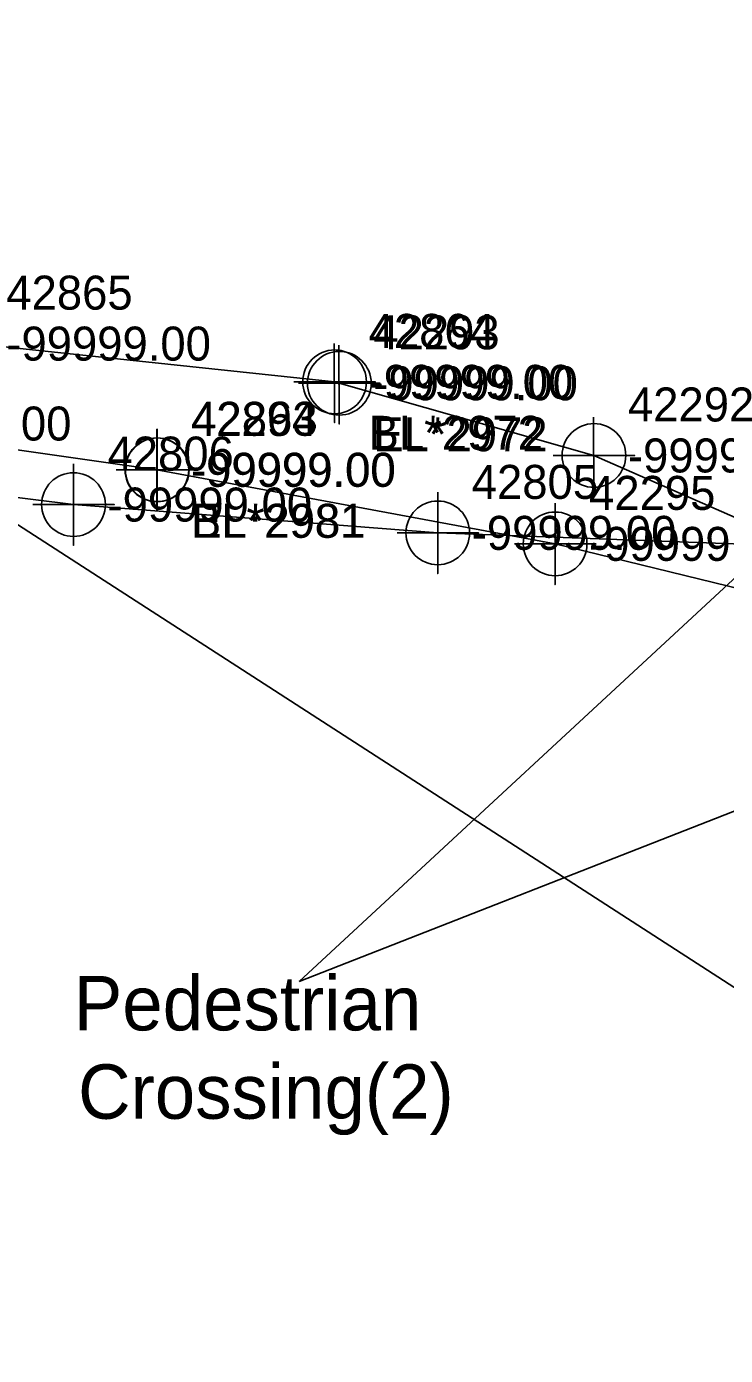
# Model space of a CAD drawing. Extents: x 2083698 to 2094313, y 743246 to 752873.
# Drawn here: x 2093623.5 to 2093674.9, y 746528.4 to 746626.1 of the extents above; entities that cross this region are included whole.
import ezdxf

# ---------------------------------------------------------------- set-up
doc = ezdxf.new("R2010")
doc.units = 0
for name, color, linetype in [('Default Symbol CELL', 7, 'Continuous'), ('Default Symbol Cogo Number', 7, 'Continuous'), ('Exist Property Corner CELL', 7, 'Continuous'), ('Exist Property Iron Pin Leader', 7, 'Continuous'), ('Exist Property Iron Pin Text', 7, 'Continuous'), ('Exist Property Line Leader', 7, 'Continuous'), ('Exist Property Monument Text', 7, 'Continuous'), ('Exist Right of Way Line Leader', 7, 'Continuous'), ('Exist Right of Way Line Text', 7, 'Continuous'), ('Exist Utilities Other Located Object Leader', 7, 'Continuous'), ('Exist Utilities Other Located Object Text', 7, 'Continuous'), ('Exist Utilities Power UG Cable SUE LOS B', 7, 'Continuous'), ('Exist Utilities Power UG Cable SUE LOS C', 7, 'Continuous'), ('Exist Utilities Telephone UG Conduit SUE LOS B', 7, 'Continuous'), ('Exist Utilities TV UG Cable SUE LOS B', 7, 'Continuous'), ('Scratch_Level_2', 7, 'Continuous'), ('Scratch_Level_3', 7, 'Continuous')]:
    doc.layers.add(name, color=color, linetype=linetype)

msp = doc.modelspace()

# ---------------------------------------------------------------- linework, layer by layer
at = {"layer": 'Exist Property Iron Pin Text'}
for points in [[(2093626.933, 746593.955), (2093626.933, 746587.955), (2093626.933, 746590.955), (2093629.933, 746590.955), (2093623.933, 746590.955)], [(2093653.741, 746591.874), (2093653.741, 746585.874), (2093653.741, 746588.874), (2093656.741, 746588.874), (2093650.741, 746588.874)]]:
    msp.add_lwpolyline(points, dxfattribs=at)
for centre in [(2093626.933, 746590.955), (2093653.741, 746588.874)]:
    msp.add_circle(centre, 2.344, dxfattribs=at)
at = {"layer": 'Exist Property Line Leader'}
for points in [[(2093633.071, 746596.51), (2093633.071, 746590.51), (2093633.071, 746593.51), (2093636.071, 746593.51), (2093630.071, 746593.51)], [(2093633.099, 746596.517), (2093633.099, 746590.517), (2093633.099, 746593.517), (2093636.099, 746593.517), (2093630.099, 746593.517)], [(2093662.377, 746591.065), (2093662.377, 746585.065), (2093662.377, 746588.065), (2093665.377, 746588.065), (2093659.377, 746588.065)]]:
    msp.add_lwpolyline(points, dxfattribs=at)
for centre in [(2093633.071, 746593.51), (2093633.099, 746593.517), (2093662.377, 746588.065)]:
    msp.add_circle(centre, 2.344, dxfattribs=at)
at = {"layer": 'Exist Right of Way Line Text'}
for points in [[(2093646.117, 746602.799), (2093646.15, 746596.984), (2093646.133, 746599.984), (2093649.15, 746599.984), (2093643.15, 746599.984)], [(2093646.462, 746602.693), (2093646.495, 746596.878), (2093646.478, 746599.878), (2093649.495, 746599.878), (2093643.495, 746599.878)], [(2093665.202, 746597.384), (2093665.235, 746591.569), (2093665.218, 746594.569), (2093668.235, 746594.569), (2093662.235, 746594.569)]]:
    msp.add_lwpolyline(points, dxfattribs=at)
for centre in [(2093646.15, 746599.984), (2093646.495, 746599.878), (2093665.235, 746594.569)]:
    msp.add_circle(centre, 2.344, dxfattribs=at)
at = {"layer": 'Exist Utilities Other Located Object Leader'}
for p in [(2093687.397, 746596.489), (2093711.996, 746582.69)]:
    msp.add_line(p, (2093643.537, 746555.868), dxfattribs=at)
at = {"layer": 'Exist Utilities Power UG Cable SUE LOS B'}
msp.add_lwpolyline([(2093491.022, 746618.597), (2093492.251, 746617.801), (2093497.044, 746616.267), (2093502.742, 746615.574), (2093516.883, 746611.38), (2093531.704, 746607.278), (2093561.622, 746601.491), (2093580.73, 746597.942), (2093602.772, 746593.943), (2093626.933, 746590.955), (2093653.741, 746588.874), (2093678.786, 746587.934), (2093688.107, 746586.976), (2093698.06, 746587.607), (2093702.807, 746588.319)], dxfattribs=at)
at = {"layer": 'Exist Utilities Power UG Cable SUE LOS C'}
msp.add_lwpolyline([(2091387.723, 747754.046), (2091459.294, 747488.138), (2091734.159, 747369.443), (2092190.287, 747172.263), (2092598.525, 747024.897), (2092972.515, 746889.782), (2093316.778, 746787.162), (2093711.239, 746532.367)], dxfattribs=at)
at = {"layer": 'Exist Utilities Telephone UG Conduit SUE LOS B'}
for points in [[(2093175.22, 746700.688), (2093176.758, 746700.983), (2093181.66, 746699.484), (2093206.905, 746693.771), (2093231.15, 746688.155), (2093256.623, 746681.959), (2093284.725, 746676.591), (2093309.603, 746671.144), (2093335.197, 746665.771), (2093361.049, 746660.734), (2093389.022, 746654.526), (2093416.973, 746647.675), (2093445.691, 746640.123), (2093473.914, 746633.194), (2093499.75, 746627.22), (2093526.174, 746622.184), (2093552.042, 746616.673), (2093579.015, 746608.454), (2093593.796, 746604.937), (2093619.488, 746602.797), (2093646.15, 746599.984)], [(2093722.343, 746560.864), (2093719.996, 746560.006), (2093715.04, 746562.375), (2093709.329, 746567.03), (2093698.957, 746576.197), (2093682.231, 746587.109), (2093665.235, 746594.569), (2093646.495, 746599.878)]]:
    msp.add_lwpolyline(points, dxfattribs=at)
at = {"layer": 'Exist Utilities TV UG Cable SUE LOS B'}
for points in [[(2093211.804, 746678.393), (2093222.599, 746675.974), (2093242.135, 746671.467), (2093264.356, 746666.243), (2093290.813, 746660.779), (2093317.395, 746655.958), (2093343.57, 746650.125), (2093367.056, 746645.407), (2093389.808, 746641.254), (2093404.728, 746638.165), (2093411.824, 746636.762), (2093419.659, 746636.764), (2093441.031, 746633.593), (2093465.697, 746628.877), (2093491.056, 746625.59), (2093517.906, 746620.208), (2093544.749, 746615.204), (2093562.294, 746605.166), (2093582.875, 746601.488), (2093609.224, 746596.916), (2093633.099, 746593.517)], [(2093633.071, 746593.51), (2093662.377, 746588.065), (2093680.365, 746583.676), (2093688.75, 746580.804), (2093702.361, 746567.68), (2093717.615, 746549.774), (2093724.021, 746533.323), (2093724.433, 746505.385), (2093724.363, 746477.486), (2093724.042, 746453.306), (2093723.688, 746427.459), (2093724.928, 746407.913), (2093725.298, 746378.395), (2093722.23, 746347.805), (2093721.14, 746321.954), (2093719.638, 746295.641), (2093717.758, 746269.047), (2093714.548, 746234.067), (2093712.697, 746215.916), (2093712.085, 746194.485), (2093710.354, 746173.749), (2093709.633, 746157.579)]]:
    msp.add_lwpolyline(points, dxfattribs=at)

# ---------------------------------------------------------------- texts
at = {"layer": 'Default Symbol CELL'}
for s, p in [('42294', (2093635.571, 746596.01)), ('42863', (2093635.599, 746596.017)), ('42295', (2093664.877, 746590.565))]:
    msp.add_text(s, height=2.5, dxfattribs=at).set_placement(p)
at = {"layer": 'Default Symbol Cogo Number'}
for p in [(2093611.724, 746595.666), (2093635.571, 746592.26), (2093635.599, 746592.267), (2093664.877, 746586.815)]:
    msp.add_text('-99999.00', height=2.5, dxfattribs=at).set_placement(p)
at = {"layer": 'Exist Property Corner CELL'}
for s, p in [('BL*2981', (2093635.571, 746588.51)), ('EL*2981', (2093635.599, 746588.517))]:
    msp.add_text(s, height=2.5, dxfattribs=at).set_placement(p)
at = {"layer": 'Exist Property Iron Pin Leader'}
for s, p in [('42806', (2093629.433, 746593.455)), ('42805', (2093656.241, 746591.374))]:
    msp.add_text(s, height=2.5, dxfattribs=at).set_placement(p)
at = {"layer": 'Exist Property Monument Text'}
for p in [(2093629.433, 746589.705), (2093656.241, 746587.624)]:
    msp.add_text('-99999.00', height=2.5, dxfattribs=at).set_placement(p)
at = {"layer": 'Exist Right of Way Line Leader'}
for s, p in [('42865', (2093621.988, 746605.297)), ('42864', (2093648.65, 746602.484)), ('42293', (2093648.995, 746602.378)), ('42292', (2093667.735, 746597.069))]:
    msp.add_text(s, height=2.5, dxfattribs=at).set_placement(p)
at = {"layer": 'Exist Utilities Other Located Object Text'}
for s, p in [('Pedestrian', (2093626.955, 746552.271)), ('Crossing(2)', (2093627.27, 746545.771))]:
    msp.add_text(s, height=4, dxfattribs=at).set_placement(p)
at = {"layer": 'Scratch_Level_2'}
for p in [(2093621.988, 746601.547), (2093648.65, 746598.734), (2093648.995, 746598.628), (2093667.735, 746593.319)]:
    msp.add_text('-99999.00', height=2.5, dxfattribs=at).set_placement(p)
at = {"layer": 'Scratch_Level_3'}
for s, p in [('BL*2972', (2093648.65, 746594.984)), ('EL*2972', (2093648.995, 746594.878))]:
    msp.add_text(s, height=2.5, dxfattribs=at).set_placement(p)

doc.saveas('drawing.dxf')
